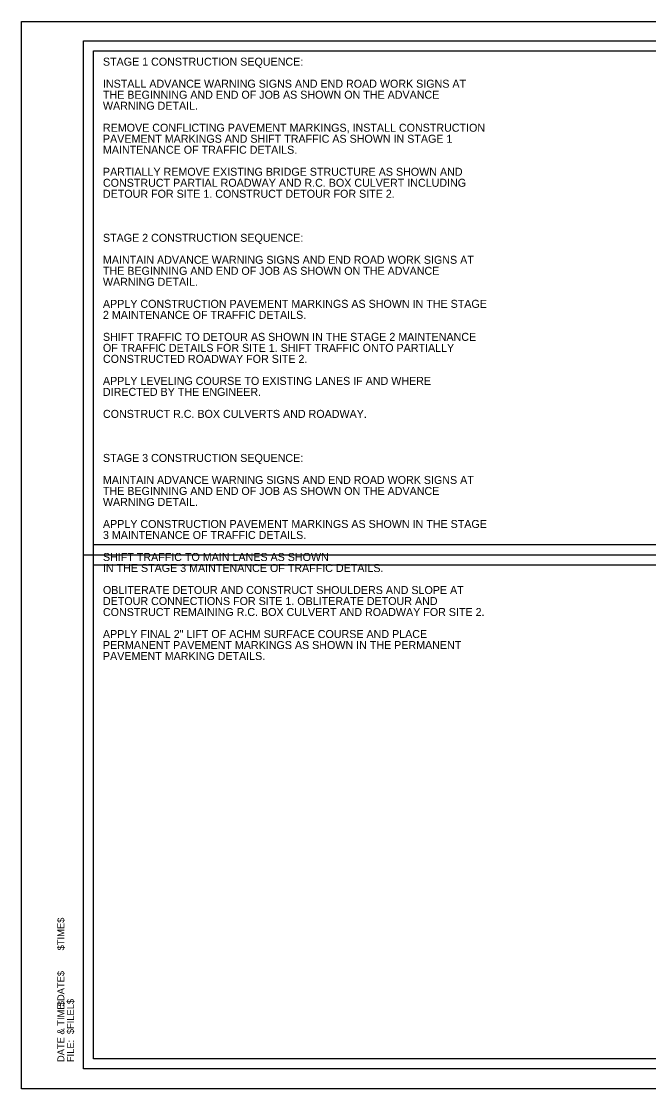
# Model space of a CAD drawing. Extents: x 1368648 to 1927880, y -1037443 to 380209.
# Drawn here: x 1369790 to 1370418, y 378686 to 379753 of the extents above; entities that cross this region are included whole.
import ezdxf

# ---------------------------------------------------------------- set-up
doc = ezdxf.new("R2010")
doc.units = 0
for name, color, linetype in [('Default', 7, 'Continuous'), ('R_Border', 7, 'Continuous'), ('R_Border Notes', 7, 'Continuous'), ('R_Border Plan-Plan', 7, 'Continuous'), ('R_No Plot', 7, 'Continuous')]:
    doc.layers.add(name, color=color, linetype=linetype)

msp = doc.modelspace()

# ---------------------------------------------------------------- linework, layer by layer
at = {"layer": 'R_Border'}
for p, q in [((1369852.4, 379733.3), (1371433.3, 379733.3)), ((1369852.4, 378706), (1369852.4, 379733.3)), ((1369852.4, 378706), (1369852.4, 378706)), ((1371433.3, 378706), (1369852.4, 378706))]:
    msp.add_line(p, q, dxfattribs=at)
at = {"layer": 'R_Border Plan-Plan'}
msp.add_line((1369852.4, 379219.6), (1371433.3, 379219.6), dxfattribs=at)
at = {"layer": 'R_No Plot'}
for points in [[(1369790.4, 379752.7), (1371457.1, 379752.7), (1371457.1, 378686), (1369790.4, 378686)], [(1371423.3, 379229.6), (1369862.4, 379229.6), (1369862.4, 379723.3), (1371110.1, 379723.3), (1371110.1, 379673.9), (1371197.8, 379673.9), (1371318.3, 379673.9), (1371318.3, 379562.2), (1371423.3, 379562.2)], [(1369862.4, 379723.3), (1371110.1, 379723.3), (1371110.1, 379673.9), (1371197.8, 379673.9), (1371318.3, 379673.9), (1371318.3, 379562.2), (1371423.3, 379562.2), (1371423.3, 378716), (1369862.4, 378716)], [(1369862.4, 379209.6), (1371423.3, 379209.6), (1371423.3, 378716), (1369862.4, 378716)]]:
    msp.add_lwpolyline(points, close=True, dxfattribs=at)

# ---------------------------------------------------------------- texts
at = {"layer": 'Default'}
for s, p in [('STAGE 1 CONSTRUCTION SEQUENCE:', (1369872, 379708.4)), ('INSTALL ADVANCE WARNING SIGNS AND END ROAD WORK SIGNS AT ', (1369872, 379686.4)), ('THE BEGINNING AND END OF JOB AS SHOWN ON THE ADVANCE ', (1369872, 379675.4)), ('WARNING DETAIL.', (1369872, 379664.4)), ('REMOVE CONFLICTING PAVEMENT MARKINGS, INSTALL CONSTRUCTION ', (1369872, 379642.4)), ('PAVEMENT MARKINGS AND SHIFT TRAFFIC AS SHOWN IN STAGE 1 ', (1369872, 379631.4)), ('MAINTENANCE OF TRAFFIC DETAILS.', (1369872, 379620.4)), ('PARTIALLY REMOVE EXISTING BRIDGE STRUCTURE AS SHOWN AND ', (1369872, 379598.4)), ('CONSTRUCT PARTIAL ROADWAY AND R.C. BOX CULVERT INCLUDING ', (1369872, 379587.4)), ('DETOUR FOR SITE 1. CONSTRUCT DETOUR FOR SITE 2. ', (1369872, 379576.4)), ('STAGE 2 CONSTRUCTION SEQUENCE:', (1369872, 379532.4)), ('MAINTAIN ADVANCE WARNING SIGNS AND END ROAD WORK SIGNS AT ', (1369872, 379510.4)), ('THE BEGINNING AND END OF JOB AS SHOWN ON THE ADVANCE ', (1369872, 379499.4)), ('WARNING DETAIL.', (1369872, 379488.4)), ('APPLY CONSTRUCTION PAVEMENT MARKINGS AS SHOWN IN THE STAGE ', (1369872, 379466.4)), ('2 MAINTENANCE OF TRAFFIC DETAILS.', (1369872, 379455.4)), ('SHIFT TRAFFIC TO DETOUR AS SHOWN IN THE STAGE 2 MAINTENANCE ', (1369872, 379433.4)), ('OF TRAFFIC DETAILS FOR SITE 1. SHIFT TRAFFIC ONTO PARTIALLY ', (1369872, 379422.4)), ('CONSTRUCTED ROADWAY FOR SITE 2.', (1369872, 379411.4)), ('APPLY LEVELING COURSE TO EXISTING LANES IF AND WHERE ', (1369872, 379389.4)), ('DIRECTED BY THE ENGINEER.', (1369872, 379378.4)), ('CONSTRUCT R.C. BOX CULVERTS AND ROADWAY.', (1369872, 379356.4)), ('STAGE 3 CONSTRUCTION SEQUENCE:', (1369872, 379312.4)), ('MAINTAIN ADVANCE WARNING SIGNS AND END ROAD WORK SIGNS AT ', (1369872, 379290.4)), ('THE BEGINNING AND END OF JOB AS SHOWN ON THE ADVANCE ', (1369872, 379279.4)), ('WARNING DETAIL.', (1369872, 379268.4)), ('APPLY CONSTRUCTION PAVEMENT MARKINGS AS SHOWN IN THE STAGE ', (1369872, 379246.4)), ('3 MAINTENANCE OF TRAFFIC DETAILS.', (1369872, 379235.4)), ('SHIFT TRAFFIC TO MAIN LANES AS SHOWN', (1369872, 379213.4)), ('IN THE STAGE 3 MAINTENANCE OF TRAFFIC DETAILS.', (1369872, 379202.4)), ('OBLITERATE DETOUR AND CONSTRUCT SHOULDERS AND SLOPE AT ', (1369872, 379180.4)), ('DETOUR CONNECTIONS FOR SITE 1. OBLITERATE DETOUR AND ', (1369872, 379169.4)), ('CONSTRUCT REMAINING R.C. BOX CULVERT AND ROADWAY FOR SITE 2.', (1369872, 379158.4)), ('APPLY FINAL 2" LIFT OF ACHM SURFACE COURSE AND PLACE ', (1369872, 379136.4)), ('PERMANENT PAVEMENT MARKINGS AS SHOWN IN THE PERMANENT ', (1369872, 379125.4)), ('PAVEMENT MARKING DETAILS.', (1369872, 379114.4))]:
    msp.add_text(s, height=8, dxfattribs=at).set_placement(p)
at = {"layer": 'R_Border Notes'}
for s, height, p in [('$TIME$', 6.98, (1369833.4, 378824.3)), ('$DATE$', 6.98, (1369833.4, 378768.4)), ('DATE & TIME:', 6.984, (1369833.4, 378712.6)), ('$FILEL$', 6.98, (1369843, 378740.5)), ('FILE: ', 6.98, (1369843, 378712.6))]:
    msp.add_text(s, height=height, rotation=90, dxfattribs=at).set_placement(p)

doc.saveas('drawing.dxf')
